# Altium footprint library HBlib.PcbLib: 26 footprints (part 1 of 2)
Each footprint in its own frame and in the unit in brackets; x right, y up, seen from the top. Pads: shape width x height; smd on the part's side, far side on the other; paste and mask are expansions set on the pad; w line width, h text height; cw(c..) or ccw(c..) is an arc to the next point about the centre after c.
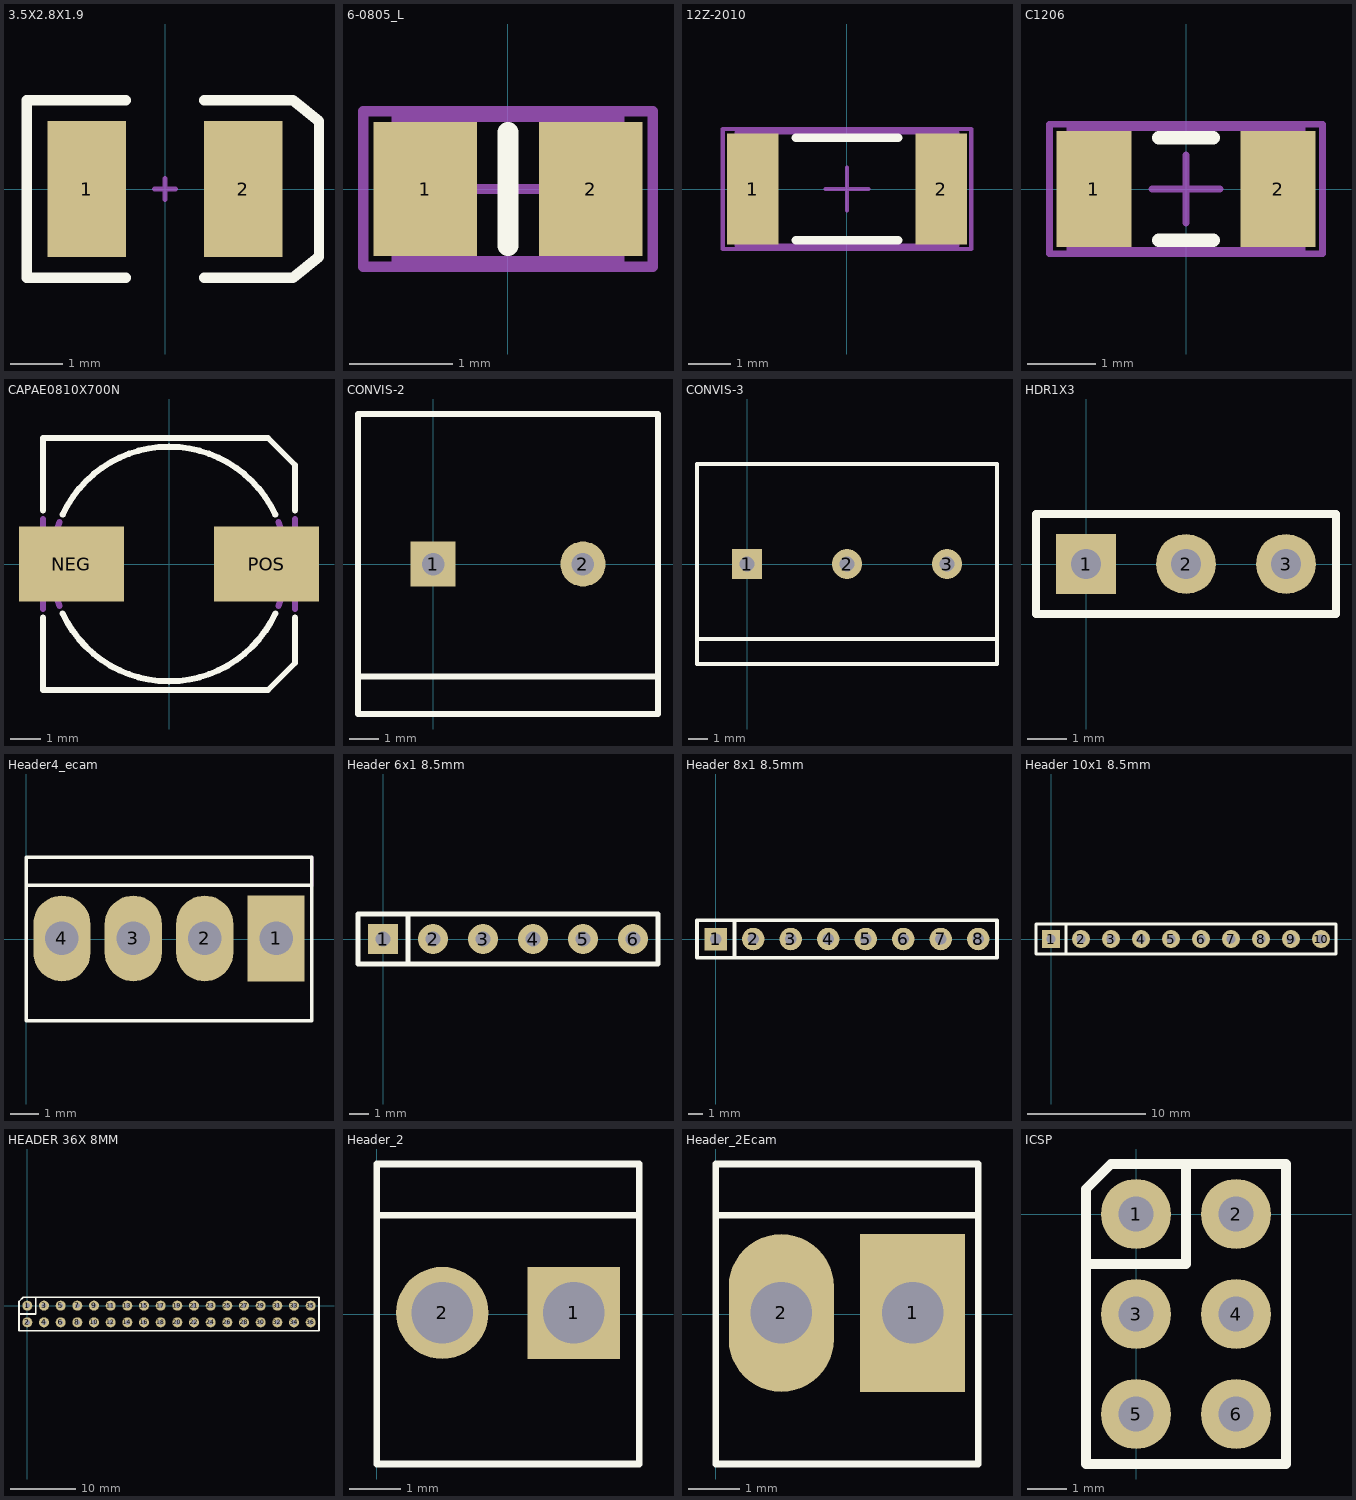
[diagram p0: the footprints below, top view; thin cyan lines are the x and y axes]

## 3.5X2.8X1.9 [mm] "SM LED; 2 C-Bend Leads; Body 3.5 x 2.8 x 1.9 mm, inc leads (LxWxH typ)"
height 1.9
pads (2):
  rect 1.5x2.6 smd: 1(-1.5,0) 2(1.5,0)
Top Overlay:
  lines w0.2: -0.75,-1.7 -2.65,-1.7 -2.65,1.7 -0.75,1.7 ; 0.75,-1.7 2.45,-1.7 2.95,-1.3 2.95,1.3 2.45,1.7 0.75,1.7
Mechanical 1:
  lines w0.1: -0.2,0 0.2,0 ; 0,-0.2 0,0.2

## 6-0805_L [mm] "Chip Resistor, Body 2.0x1.2mm, IPC High Density"
height 0.7
pads (2):
  rect 1x1.3 smd: 1(-0.8,0) 2(0.8,0)
Top Overlay:
  lines w0.2: 0,-0.55 0,0.55
Mechanical 13:
  lines w0.1: -1.075,-0.7 1.075,-0.7 1.075,0.7 -1.075,0.7 -1.075,-0.7
Mechanical 15:
  lines w0.1: -0.5,0 0.5,0 ; 0,-0.5 0,0.5 ; -1.4,-0.75 1.4,-0.75 1.4,0.75 -1.4,0.75 -1.4,-0.75
3D body: height 0.7, standoff 0, extent -1.075,-0.7 1.075,0.7

## 12Z-2010 [mm] "Chip Resistor, Body 5.0x2.5mm, IPC High Density"
height 0.9
pads (2):
  rect 1.2x2.6 smd: 1(-2.2,0) 2(2.2,0)
Top Overlay:
  lines w0.2: -1.2,-1.2 1.2,-1.2 ; -1.2,1.2 1.2,1.2
Mechanical 13:
  lines w0.1: -2.575,-1.325 2.575,-1.325 2.575,1.325 -2.575,1.325 -2.575,-1.325
Mechanical 15:
  lines w0.1: -0.5,0 0.5,0 ; 0,-0.5 0,0.5 ; -2.9,-1.4 2.9,-1.4 2.9,1.4 -2.9,1.4 -2.9,-1.4
3D body: height 0.9, standoff 0, extent -2.575,-1.325 2.575,1.325

## C1206 [mm] "Chip Capacitor, Body 3.2x1.6mm, IPC High Density"
height 1.3
pads (2):
  rect 1.1x1.7 smd: 1(-1.35,0) 2(1.35,0)
Top Overlay:
  lines w0.2: -0.4,-0.75 0.4,-0.75 ; -0.4,0.75 0.4,0.75
Mechanical 13:
  lines w0.1: -1.7,-0.9 -1.7,0.9 1.7,0.9 1.7,-0.9 -1.7,-0.9
Mechanical 15:
  lines w0.1: -0.5,0 0.5,0 ; 0,-0.5 0,0.5 ; -2,-0.95 -2,0.95 2,0.95 2,-0.95 -2,-0.95
3D body: height 1.3, standoff 0, extent -1.7,-0.9 1.7,0.9

## CAPAE0810X700N [mm]
pads (2):
  rect 3.5x2.5 smd: NEG(-3.25,0) POS(3.25,0)
Top Overlay:
  lines w0.203: -4.2,-1.778 -4.2,-4.2 3.3,-4.2 4.2,-3.3 4.2,-1.778 ; -4.2,1.778 -4.2,4.2 3.3,4.2 4.2,3.3 4.2,1.778 ; -3.546,-1.646 ccw(c0,0) 3.546,-1.646 ; -3.543,1.652 cw(c0,0) 3.543,1.652
Mechanical 4:
  lines w0.203: -4.2,-1.5 -4.2,1.5 -4.2,-1.5 ; -3.65,-1.401 cw(c0,0) -3.65,1.401 ccw(c0,0) -3.65,-1.401 ; 3.65,-1.401 ccw(c0,0) 3.65,1.401 cw(c0,0) 3.65,-1.401 ; 4.2,-1.5 4.2,1.5 4.2,-1.5

## CONVIS-2 [mil] "Connecteur à vis 2 contacts Pitch 5.08"
height 590.55
pads (2):
  rect 60x60 hole 30: 1(0,0)
  round 60 hole 30: 2(200,0)
Top Overlay:
  lines w8: -100,-150 300,-150 ; -100,-200 300,-200 300,200 100,200 -100,200 -100,-200

## CONVIS-3 [mil] "Connecteur à vis 3 contacts Pitch 5.08"
height 590.55
pads (3):
  rect 60x60 hole 30: 1(0,0)
  round 60 hole 30: 2(200,0) 3(400,0)
Top Overlay:
  lines w8: -100,-150 500,-150 ; -100,-200 500,-200 500,200 -100,200 -100,-200

## HDR1X3 [mil] "Connector; Header; 3 Position"
pads (3):
  rect 60x60 hole 30: 1(0,0)
  round 60 hole 30: 2(100,0) 3(200,0)
Top Overlay:
  lines w7.87: -50,-50 250,-50 250,50 -50,50 -50,-50

## Header4_ecam [mil]
pads (4):
  rect 80x120 hole 46.85: 1(350,0.79)
  oval 80x120 hole 46.85: 2(250,0.79) 3(150,0.79) 4(50,0.79)
Top Overlay:
  lines w5: 0,75 400,75 ; 0,-114.17 400,-114.17 400,114.17 0,114.17 0,-114.17
Mechanical 4:
  circle w7.87: c350,0 r3.94
  circle w7.87: c350,0 r3.94
  lines w5: 400,74.8 400,114.17

## Header 6x1 8.5mm [mil] "Stackable 6 pin header"
pads (6):
  rect 60x60 hole 30: 1(0,0)
  round 60 hole 30: 2(100,0) 3(200,0) 4(300,0) 5(400,0) 6(500,0)
Top Overlay:
  lines w10: 50,-50 -50,-50 -50,0 -50,50 50,50 ; 50,-50 50,50 ; 50,-50 550,-50 550,50 50,50
3D body "SIL_Socket06.stp": height 334.65, standoff -584.65, extent -49.99,-49.99 550.01,50.01

## Header 8x1 8.5mm [mil] "Stackable 8 pin header"
pads (8):
  rect 60x60 hole 30: 1(0,0)
  round 60 hole 30: 2(100,0) 3(200,0) 4(300,0) 5(400,0) 6(500,0) 7(600,0) 8(700,0)
Top Overlay:
  lines w10: 50,-50 50,50 ; -50,-50 -50,50 750,50 750,-50 -50,-50
3D body "SIL_Socket08_.stp": height 334.65, standoff -584.65, extent -50,-49.99 750,50.01

## Header 10x1 8.5mm [mil] "Stackable 10 pin header"
pads (10):
  rect 60x60 hole 30: 1(0,0)
  round 60 hole 30: 2(100,0) 3(200,0) 4(300,0) 5(400,0) 6(500,0) 7(600,0) 8(700,0) 9(800,0) 10(900,0)
Top Overlay:
  lines w10: 50,-50 50,50 ; 50,-50 950,-50 950,50 50,50 ; 50,-50 -50,-50 -50,50 50,50
3D body "SIL_Socket10.stp": height 334.65, standoff -584.65, extent -50,-50 950,50

## HEADER 36X 8MM [mil] "Stackable 10 pin header"
pads (36):
  round 60 hole 30: 1(0,0) 2(0,-100) 3(100,0) 4(100,-100) 5(200,0) 6(200,-100) 7(300,0) 8(300,-100) 9(400,0) 10(400,-100) 11(500,0) 12(500,-100) 13(600,0) 14(600,-100) 15(700,0) 16(700,-100) 17(800,0) 18(800,-100) 19(900,0) 20(900,-100) 21(1000,0) 22(1000,-100) 23(1100,0) 24(1100,-100) 25(1200,0) 26(1200,-100) 27(1300,0) 28(1300,-100) 29(1400,0) 30(1400,-100) 31(1500,0) 32(1500,-100) 33(1600,0) 34(1600,-100) 35(1700,0) 36(1700,-100)
Top Overlay:
  lines w10: -50,-50 50,-50 50,50 ; -50,-150 -50,25 -25,50 1750,50 1750,-150 -50,-150
3D body "SIL_Socket36.stp": height 334.65, standoff -584.65, extent -50,-150 1750,50

## Header_2 [mm]
pads (2):
  rect 1.785x1.785 hole 1.19: 1(3.81,0.02)
  round 1.785 hole 1.19: 2(1.27,0.02)
Top Overlay:
  lines w0.127: 0,1.905 5.08,1.905 ; 0,-2.9 5.08,-2.9 5.08,0 5.08,2.9 0,2.9 0,-2.9

## Header_2Ecam [mil]
pads (2):
  rect 80x120 hole 46.85: 1(150,0.79)
  oval 80x120 hole 46.85: 2(50,0.79)
Top Overlay:
  lines w5: 0,75 200,75 ; 0,-114.17 200,-114.17 200,0 200,114.17 0,114.17 0,-114.17

## ICSP [mil]
pads (6):
  round 70 hole 35.43: 1(0,0) 2(100,0) 3(0,-100) 4(100,-100) 5(0,-200) 6(100,-200)
Top Overlay:
  lines w10: -50,-50 50,-50 50,50 ; -50,-250 150,-250 150,50 -25,50 -50,25 -50,-250
3D body "ICSP.stp": height 484.65, standoff -105.84, extent -49.99,-249.99 150.01,50.01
